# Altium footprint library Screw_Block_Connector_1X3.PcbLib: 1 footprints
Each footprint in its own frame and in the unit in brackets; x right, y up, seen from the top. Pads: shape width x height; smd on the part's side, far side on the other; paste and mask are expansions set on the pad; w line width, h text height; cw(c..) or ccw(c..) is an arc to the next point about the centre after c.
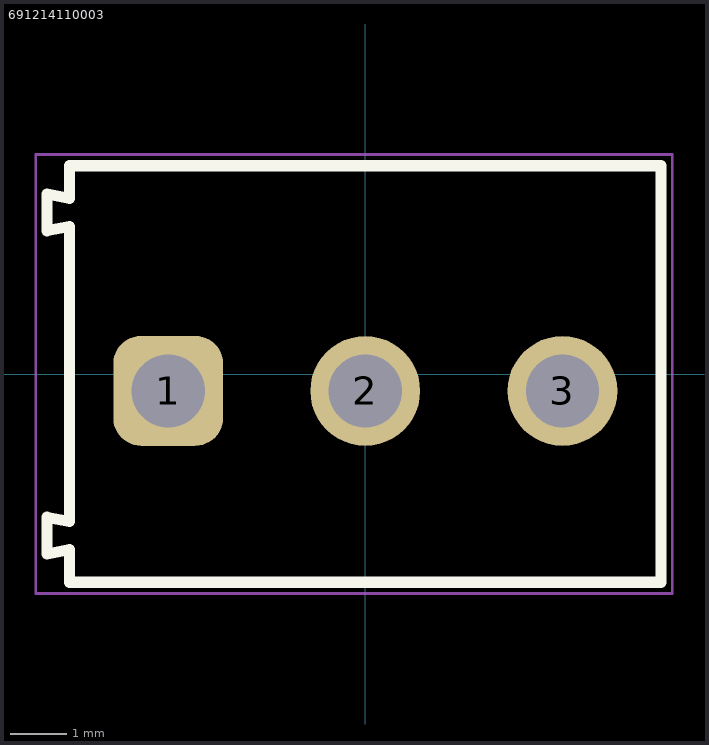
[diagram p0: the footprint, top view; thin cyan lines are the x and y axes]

## 691214110003 [mm] "3.50 mm Horizontal Entry Modular, 3p"
height 8.5
pads (3):
  rrect50% 1.95x1.95 hole 1.3: 1(-3.5,-0.3)
  round 1.95 hole 1.3: 2(0,-0.3) 3(3.5,-0.3)
Top Overlay:
  lines w0.2: -5.65,-3.195 -5.65,-2.545 -5.25,-2.62 -5.25,2.62 -5.65,2.545 -5.65,3.195 -5.25,3.12 -5.25,3.7 5.25,3.7 5.25,-3.7 -5.25,-3.7 -5.25,-3.12 -5.65,-3.195
Top Assembly:
  lines w0.1: -5.65,-3.195 -5.25,-3.12 -5.25,-3.7 5.25,-3.7 5.25,3.7 -5.25,3.7 -5.25,3.12 -5.65,3.195 -5.65,2.545 -5.25,2.62 -5.25,-2.62 -5.65,-2.545 -5.65,-3.195
Top Designator:
  text ".Designator" at -3.647,-0.357 h1
Top 3D Body:
  lines w0.1: -5.65,-3.195 -5.65,-2.545 -5.25,-2.62 -5.25,2.62 -5.65,2.545 -5.65,3.195 -5.25,3.12 -5.25,3.7 5.25,3.7 5.25,-3.7 -5.25,-3.7 -5.25,-3.12 -5.65,-3.195
Top Courtyard:
  lines w0.05: -5.85,-3.9 -5.85,3.9 5.45,3.9 5.45,-3.9 -5.85,-3.9
Top Component Center:
  lines w0.1: -0.5,0 0.5,0 ; 0,-0.5 0,0.5
3D body "691214110003.stp": height 8.55, standoff -3.65, extent -5.7,-3.7 5.25,3.7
